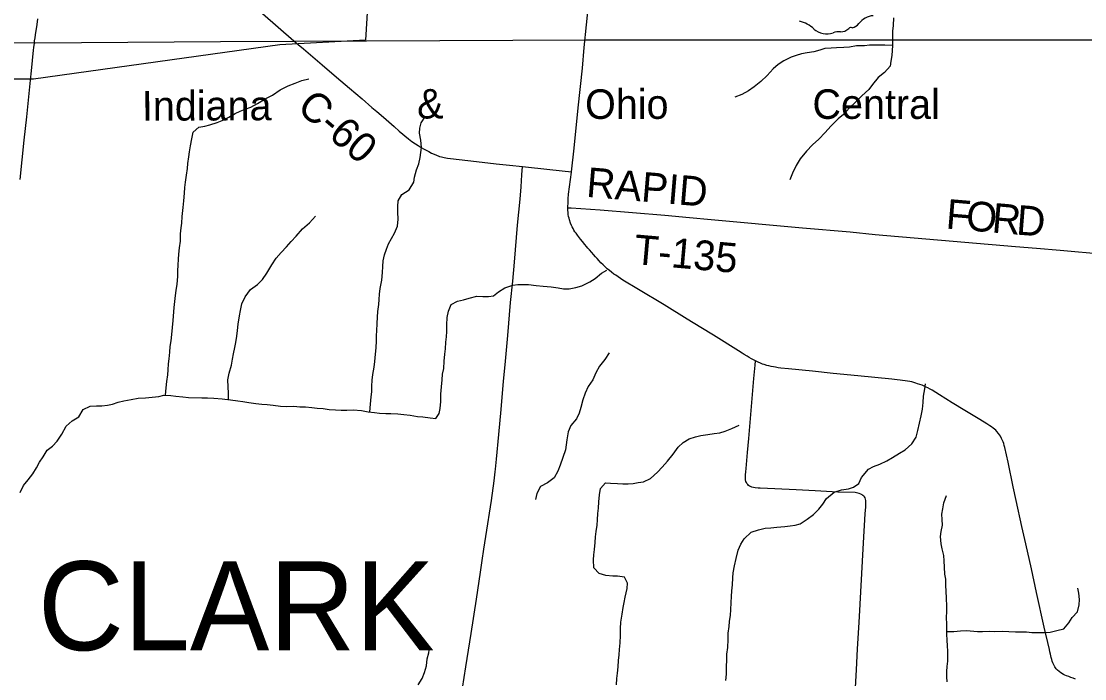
# Model space of a CAD drawing. Extents: x 1442749 to 1756758, y 235267 to 677782.
# Drawn here: x 1596416 to 1607177, y 476949 to 483604 of the extents above; entities that cross this region are included whole.
import ezdxf

# ---------------------------------------------------------------- set-up
doc = ezdxf.new("R2010")
doc.units = 0
for name, color, linetype in [('GM_X_City_Street', 7, 'Continuous'), ('GM_X_Corporation', 7, 'Continuous'), ('GM_X_County_Road', 7, 'Continuous'), ('GM_X_County_Road_Text', 7, 'Continuous'), ('GM_X_Minor_River', 7, 'Continuous'), ('GM_X_Rail_Line', 7, 'Continuous'), ('GM_X_Rail_Line_Text', 7, 'Continuous'), ('GM_X_State_Route', 7, 'Continuous'), ('GM_X_State_Shield', 7, 'Continuous'), ('GM_X_Township_Road', 7, 'Continuous'), ('GM_X_Township_Road_Text', 7, 'Continuous'), ('GM_X_Township_Text', 7, 'Continuous')]:
    doc.layers.add(name, color=color, linetype=linetype)

msp = doc.modelspace()

# ---------------------------------------------------------------- linework, layer by layer
at = {"layer": 'GM_X_City_Street'}
for points in [[(1598415, 484068), (1598535, 483962), (1598604, 483902), (1598646, 483865), (1598760, 483766), (1598857, 483682), (1599175, 483407), (1599219, 483370)], [(1596520, 483102), (1596541, 483311), (1596544, 483338), (1596550, 483383), (1596552, 483406), (1596556, 483437), (1596560, 483467), (1596563, 483490), (1596569, 483527), (1596576, 483571), (1596585, 483629)]]:
    msp.add_lwpolyline(points, dxfattribs=at)
at = {"layer": 'GM_X_Corporation'}
msp.add_lwpolyline([(1595505, 486015), (1596757, 485922), (1597610, 485853), (1597573, 485513), (1598676, 485417), (1598643, 485013), (1599988, 484861), (1599899, 483414), (1599034, 483364), (1596541, 483017), (1595600, 483017), (1595370, 485047)], close=True, dxfattribs=at)
at = {"layer": 'GM_X_County_Road'}
for points in [[(1599219, 483370), (1599271, 483325)], [(1599271, 483325), (1599462, 483163), (1599607, 483039), (1599739, 482927), (1599867, 482818), (1599965, 482732), (1600013, 482691), (1600080, 482633), (1600188, 482538), (1600240, 482493), (1600334, 482415), (1600370, 482387), (1600405, 482363), (1600432, 482346), (1600464, 482327), (1600487, 482314), (1600519, 482296), (1600540, 482285), (1600568, 482270), (1600611, 482251), (1600648, 482237), (1600667, 482231), (1600696, 482225), (1600730, 482220), (1600761, 482215), (1600846, 482204), (1601022, 482184), (1601220, 482161), (1601357, 482147), (1601488, 482133), (1601488, 482133)], [(1596405, 482001), (1596445, 482400), (1596472, 482638), (1596510, 483007), (1596520, 483102)], [(1600882, 476853), (1600915, 477070), (1600968, 477407), (1601021, 477754), (1601062, 478027), (1601081, 478147), (1601098, 478260), (1601118, 478390), (1601173, 478753), (1601201, 478951), (1601212, 479045), (1601215, 479072), (1601219, 479106), (1601225, 479173), (1601247, 479421), (1601271, 479676), (1601297, 479960), (1601312, 480127), (1601339, 480424), (1601368, 480757), (1601389, 480973), (1601408, 481165), (1601438, 481541), (1601463, 481802), (1601473, 481930), (1601482, 482051), (1601488, 482133)], [(1601488, 482133), (1601765, 482103), (1601984, 482079)], [(1604841, 476563), (1604867, 477038), (1604879, 477251), (1604894, 477520), (1604940, 478325), (1604957, 478620), (1604962, 478689), (1604963, 478716), (1604963, 478736), (1604962, 478753), (1604959, 478768), (1604955, 478780), (1604949, 478789), (1604941, 478798), (1604933, 478805), (1604924, 478812), (1604912, 478818), (1604896, 478825), (1604880, 478829), (1604868, 478831), (1604853, 478833), (1604679, 478839), (1604450, 478851), (1604256, 478860), (1604040, 478870), (1603892, 478878), (1603873, 478880), (1603843, 478883), (1603825, 478885), (1603809, 478889), (1603796, 478894), (1603786, 478900), (1603776, 478906), (1603767, 478915), (1603758, 478927), (1603753, 478937), (1603749, 478947), (1603746, 478962), (1603745, 478972), (1603744, 478984), (1603744, 479000), (1603745, 479013), (1603747, 479043), (1603751, 479079), (1603765, 479239), (1603777, 479382), (1603829, 479987), (1603843, 480124), (1603847, 480166)]]:
    msp.add_lwpolyline(points, dxfattribs=at)
at = {"layer": 'GM_X_Minor_River'}
for points in [[(1605241, 483638), (1605238, 483562), (1605233, 483503), (1605231, 483441), (1605232, 483359), (1605229, 483307), (1605224, 483257), (1605215, 483199), (1605209, 483149), (1605152, 483086), (1605087, 483034), (1605030, 482965), (1604993, 482913), (1604920, 482850), (1604857, 482785), (1604798, 482729), (1604737, 482662), (1604682, 482615), (1604607, 482541), (1604550, 482478), (1604485, 482411), (1604422, 482353), (1604361, 482288), (1604298, 482211), (1604257, 482143), (1604220, 482067)], [(1605232, 483359), (1605155, 483362), (1605069, 483361), (1604999, 483362), (1604949, 483357), (1604867, 483354), (1604796, 483343), (1604738, 483338), (1604666, 483336), (1604612, 483333), (1604547, 483328), (1604497, 483311), (1604435, 483295), (1604368, 483284), (1604312, 483273), (1604258, 483258), (1604205, 483240), (1604133, 483203), (1604076, 483166), (1604025, 483124), (1603964, 483055), (1603901, 482994), (1603832, 482940), (1603774, 482899), (1603707, 482864), (1603638, 482835)], [(1597875, 479818), (1597882, 479895), (1597891, 479957), (1597899, 480025), (1597904, 480075), (1597907, 480137), (1597914, 480187), (1597921, 480255), (1597923, 480311), (1597932, 480369), (1597941, 480435), (1597948, 480503), (1597953, 480577), (1597965, 480707), (1597971, 480767), (1597978, 480829), (1597985, 480879), (1597994, 480943), (1597999, 481020), (1598002, 481078), (1598004, 481134), (1598007, 481196), (1598012, 481246), (1598017, 481312), (1598026, 481380), (1598029, 481452), (1598036, 481512), (1598040, 481562), (1598045, 481628), (1598054, 481718), (1598061, 481788), (1598068, 481865), (1598073, 481923), (1598078, 481977), (1598087, 482045), (1598098, 482115), (1598102, 482165), (1598111, 482231), (1598118, 482283), (1598129, 482345), (1598142, 482413), (1598155, 482483), (1598214, 482532), (1598274, 482543), (1598324, 482555), (1598397, 482578), (1598465, 482607), (1598516, 482632), (1598580, 482672), (1598631, 482693), (1598681, 482716), (1598740, 482736), (1598808, 482771), (1598883, 482818), (1598958, 482855), (1599035, 482910), (1599116, 482951), (1599188, 482978), (1599257, 483006), (1599327, 483021)], [(1599945, 479650), (1599949, 479728), (1599958, 479802), (1599963, 479854), (1599964, 479912), (1599966, 479970), (1599975, 480030), (1599986, 480104), (1599995, 480160), (1600002, 480234), (1600007, 480300), (1600010, 480368), (1600011, 480422), (1600013, 480472), (1600018, 480546), (1600021, 480609), (1600026, 480665), (1600035, 480737), (1600037, 480787), (1600040, 480843), (1600047, 480899), (1600064, 480983), (1600073, 481061), (1600074, 481121), (1600079, 481181), (1600092, 481239), (1600112, 481297), (1600131, 481351), (1600162, 481404), (1600193, 481460), (1600222, 481530), (1600231, 481602), (1600228, 481672), (1600226, 481730), (1600231, 481788), (1600268, 481852), (1600341, 481899), (1600390, 481975), (1600395, 482025), (1600414, 482101), (1600439, 482161), (1600454, 482224), (1600467, 482325), (1600460, 482401), (1600445, 482473), (1600450, 482523), (1600464, 482575), (1600505, 482643)], [(1604220, 482067), (1604193, 482000)], [(1598512, 479776), (1598513, 479840), (1598510, 479905), (1598508, 479975), (1598521, 480043), (1598545, 480125), (1598555, 480183), (1598564, 480237), (1598579, 480301), (1598588, 480353), (1598597, 480417), (1598603, 480473), (1598612, 480539), (1598623, 480623), (1598634, 480677), (1598649, 480745), (1598682, 480816), (1598737, 480888), (1598808, 480939), (1598859, 480990), (1598900, 481056), (1598951, 481140), (1598994, 481207), (1599045, 481265), (1599100, 481320), (1599149, 481374), (1599198, 481429), (1599263, 481502), (1599334, 481564), (1599393, 481633)], [(1600646, 479634), (1600655, 479686), (1600661, 479756), (1600662, 479831), (1600667, 479905), (1600674, 479975), (1600679, 480033), (1600692, 480091), (1600695, 480163), (1600702, 480235), (1600709, 480287), (1600714, 480355), (1600718, 480411), (1600721, 480465), (1600724, 480533), (1600727, 480605), (1600738, 480671), (1600767, 480739), (1600829, 480770), (1600892, 480784), (1600950, 480803), (1601027, 480822), (1601087, 480819), (1601143, 480819), (1601195, 480826), (1601246, 480865), (1601308, 480905), (1601389, 480934), (1601441, 480939), (1601497, 480940), (1601550, 480940), (1601626, 480931), (1601696, 480922), (1601778, 480915), (1601848, 480906), (1601904, 480897), (1601960, 480896), (1602029, 480911), (1602087, 480927), (1602168, 480968), (1602222, 481001), (1602287, 481056), (1602340, 481086)], [(1602365, 480249), (1602320, 480182), (1602267, 480114), (1602230, 480047), (1602201, 479975), (1602154, 479907), (1602121, 479840), (1602100, 479772), (1602077, 479694), (1602062, 479638), (1602033, 479580), (1601976, 479513), (1601949, 479447), (1601938, 479369), (1601931, 479317), (1601924, 479265), (1601897, 479189), (1601868, 479111), (1601845, 479050), (1601810, 478982), (1601742, 478933), (1601669, 478896), (1601632, 478826), (1601619, 478762)], [(1603593, 477592), (1603596, 477648), (1603601, 477720), (1603603, 477782), (1603606, 477838), (1603613, 477900), (1603618, 477970), (1603621, 478020), (1603634, 478092), (1603651, 478166), (1603670, 478250), (1603697, 478312), (1603732, 478366), (1603803, 478433), (1603877, 478458), (1603944, 478475), (1604000, 478478), (1604062, 478482), (1604144, 478491), (1604197, 478496), (1604247, 478503), (1604299, 478519), (1604368, 478564), (1604431, 478611), (1604488, 478667), (1604526, 478718), (1604563, 478774), (1604640, 478839), (1604715, 478860), (1604787, 478871), (1604837, 478887), (1604892, 478926), (1604919, 478988), (1604990, 479071), (1605041, 479096), (1605103, 479122), (1605176, 479155), (1605233, 479190), (1605303, 479231), (1605360, 479267), (1605429, 479328), (1605472, 479393), (1605489, 479463), (1605504, 479537), (1605523, 479609), (1605534, 479679), (1605543, 479745), (1605546, 479811), (1605559, 479883), (1605565, 479933)], [(1596406, 478835), (1596439, 478907), (1596485, 478963), (1596532, 479022), (1596571, 479084), (1596602, 479140), (1596637, 479197), (1596678, 479263), (1596731, 479302), (1596781, 479354), (1596827, 479425), (1596872, 479505), (1596931, 479560), (1596999, 479601), (1597044, 479675), (1597115, 479708), (1597179, 479711), (1597231, 479711), (1597288, 479718), (1597338, 479729), (1597398, 479749), (1597453, 479762), (1597527, 479777), (1597599, 479788), (1597672, 479791), (1597740, 479800), (1597808, 479807), (1597859, 479819), (1597929, 479816), (1597981, 479811), (1598051, 479802), (1598107, 479796), (1598243, 479794), (1598301, 479791), (1598366, 479790), (1598450, 479783), (1598534, 479774), (1598608, 479761), (1598660, 479754), (1598720, 479747), (1598790, 479737), (1598850, 479730), (1598906, 479725), (1598964, 479720), (1599040, 479709), (1599105, 479706), (1599175, 479708), (1599235, 479703), (1599291, 479700), (1599355, 479695), (1599409, 479688), (1599471, 479684), (1599533, 479675), (1599595, 479670), (1599654, 479667), (1599710, 479669), (1599776, 479670), (1599858, 479663), (1599926, 479652), (1599992, 479645), (1600042, 479638), (1600104, 479633), (1600156, 479633), (1600227, 479630), (1600287, 479625), (1600351, 479618), (1600427, 479605), (1600479, 479600), (1600553, 479589), (1600611, 479583), (1600646, 479634)], [(1602558, 478922), (1602608, 478927), (1602660, 478937), (1602714, 478944), (1602783, 478977), (1602854, 479039), (1602901, 479090), (1602956, 479153), (1603013, 479223), (1603062, 479292), (1603115, 479342), (1603175, 479377), (1603238, 479398), (1603294, 479412), (1603362, 479421), (1603427, 479430), (1603485, 479437), (1603539, 479455), (1603606, 479482), (1603679, 479517)], [(1602438, 476887), (1602443, 476951), (1602450, 477005), (1602457, 477071), (1602460, 477133), (1602467, 477191), (1602469, 477246), (1602476, 477314), (1602481, 477388), (1602480, 477458), (1602483, 477522), (1602496, 477604), (1602507, 477670), (1602516, 477722), (1602528, 477774), (1602546, 477864), (1602552, 477918), (1602521, 477978), (1602451, 477987), (1602401, 477988), (1602333, 477993), (1602265, 478014), (1602211, 478073), (1602205, 478153), (1602209, 478203), (1602218, 478259), (1602225, 478329), (1602228, 478385), (1602234, 478439), (1602243, 478505), (1602248, 478559), (1602251, 478623), (1602256, 478677), (1602260, 478740), (1602267, 478812), (1602276, 478876), (1602329, 478931), (1602379, 478928), (1602451, 478925), (1602502, 478923), (1602558, 478922)], [(1605786, 476918), (1605783, 476968), (1605781, 477022), (1605786, 477074), (1605791, 477128), (1605792, 477229), (1605789, 477281), (1605786, 477339), (1605782, 477399), (1605783, 477451), (1605782, 477501), (1605779, 477569), (1605783, 477630), (1605780, 477688), (1605777, 477760), (1605776, 477838), (1605773, 477890), (1605770, 477956), (1605762, 478007), (1605759, 478079), (1605756, 478143), (1605751, 478197), (1605734, 478264), (1605726, 478314), (1605719, 478390), (1605726, 478440), (1605739, 478504), (1605736, 478560), (1605732, 478614), (1605741, 478670), (1605750, 478730), (1605779, 478804)], [(1605783, 477427), (1605851, 477428), (1605919, 477433), (1605979, 477437), (1606092, 477427), (1606144, 477428), (1606210, 477430), (1606268, 477429), (1606344, 477432), (1606409, 477429), (1606477, 477424), (1606589, 477423), (1606641, 477418), (1606711, 477417), (1606771, 477418), (1606828, 477422), (1606896, 477437), (1606964, 477454), (1607017, 477515), (1607050, 477569), (1607103, 477628), (1607122, 477698), (1607125, 477750), (1607118, 477815), (1607106, 477867)], [(1603546, 476931), (1603553, 476995), (1603552, 477077), (1603555, 477133), (1603556, 477197), (1603565, 477267), (1603568, 477346), (1603570, 477410), (1603579, 477478), (1603584, 477530), (1603593, 477592)], [(1600433, 476887), (1600472, 476953), (1600495, 477011), (1600516, 477080), (1600525, 477150), (1600539, 477212), (1600546, 477264)]]:
    msp.add_lwpolyline(points, dxfattribs=at)
at = {"layer": 'GM_X_Rail_Line'}
msp.add_lwpolyline([(1571148, 478363), (1571889, 478539), (1575743, 479319), (1579466, 480096), (1583642, 480978), (1587511, 481783), (1590382, 482359), (1593451, 482999), (1594964, 483308), (1595339, 483357), (1595650, 483379), (1596034, 483391), (1596557, 483385), (1598434, 483400), (1602128, 483416), (1606202, 483416), (1608267, 483417), (1610514, 483462), (1613925, 483518), (1615664, 483549), (1619432, 483601)], dxfattribs=at)
at = {"layer": 'GM_X_State_Route'}
msp.add_lwpolyline([(1607084, 476945), (1607060, 476954), (1607035, 476963), (1607015, 476971), (1606992, 476980), (1606976, 476987), (1606962, 476994), (1606936, 477009), (1606917, 477023), (1606902, 477036), (1606888, 477051), (1606875, 477071), (1606863, 477091), (1606854, 477112), (1606848, 477129), (1606843, 477144), (1606838, 477164), (1606834, 477182), (1606830, 477198), (1606825, 477221), (1606819, 477246), (1606768, 477473), (1606690, 477822), (1606638, 478063), (1606581, 478316), (1606541, 478491), (1606484, 478754), (1606454, 478892), (1606401, 479142), (1606368, 479290), (1606362, 479310), (1606357, 479330), (1606350, 479347), (1606346, 479361), (1606336, 479382), (1606324, 479404), (1606315, 479418), (1606306, 479431), (1606287, 479453), (1606276, 479464), (1606263, 479475), (1606249, 479487), (1606233, 479498), (1606217, 479510), (1606187, 479529), (1606117, 479572), (1605965, 479664), (1605837, 479743), (1605709, 479824), (1605634, 479870), (1605613, 479881), (1605591, 479893), (1605573, 479902), (1605552, 479911), (1605531, 479920), (1605510, 479928), (1605486, 479936), (1605467, 479942), (1605447, 479947), (1605426, 479953), (1605407, 479957), (1605384, 479961), (1605359, 479965), (1605333, 479969), (1605310, 479972), (1605278, 479976), (1605251, 479979), (1605224, 479981), (1604882, 480015), (1604631, 480040), (1604422, 480061), (1604181, 480085), (1604102, 480094), (1604074, 480098), (1604047, 480102), (1604027, 480106), (1604005, 480110), (1603982, 480115), (1603960, 480121), (1603935, 480129), (1603916, 480135), (1603895, 480144), (1603873, 480153), (1603854, 480163), (1603847, 480166), (1603832, 480174), (1603805, 480188), (1603783, 480201), (1603762, 480213), (1603732, 480231), (1603710, 480245), (1603675, 480267), (1603420, 480426), (1603292, 480505), (1603155, 480589), (1602920, 480733), (1602662, 480890), (1602505, 480985), (1602455, 481017), (1602431, 481033), (1602411, 481046), (1602389, 481063), (1602367, 481080), (1602344, 481100), (1602320, 481122), (1602303, 481138), (1602282, 481159), (1602264, 481179), (1602242, 481202), (1602226, 481220), (1602205, 481244), (1602188, 481264), (1602165, 481291), (1602149, 481309), (1602137, 481324), (1602120, 481344), (1602095, 481375), (1602074, 481400), (1602043, 481439), (1602030, 481459), (1602019, 481474), (1602009, 481491), (1602000, 481506), (1601992, 481523), (1601984, 481538), (1601974, 481562), (1601963, 481594), (1601959, 481611), (1601954, 481629), (1601951, 481649), (1601949, 481671), (1601948, 481689), (1601947, 481712), (1601947, 481717), (1601947, 481732), (1601949, 481759), (1601950, 481784), (1601951, 481806), (1601955, 481853), (1601963, 481928), (1601983, 482078), (1601984, 482079), (1602012, 482319), (1602053, 482727), (1602094, 483131), (1602113, 483337), (1602136, 483569), (1602161, 483833)], dxfattribs=at)
at = {"layer": 'GM_X_State_Shield'}
for centre, radius, start, end in [((1604210, 483281), 334, 47.1842, 75.836), ((1604797, 483653), 119, 282.8732, 323.2771), ((1605053, 483459), 202, 94.4031, 142.5768), ((1604571, 483689), 212, 230.7004, 286.2918), ((1604693, 483324), 174, 85.6951, 111.2099), ((1604708, 483610), 113, 268.777, 315.5493), ((1604811, 483508), 31.8, 65.7517, 132.6484)]:
    msp.add_arc(centre, radius, start, end, dxfattribs=at)
at = {"layer": 'GM_X_Township_Road'}
msp.add_lwpolyline([(1601947, 481717), (1601980, 481715), (1602275, 481696), (1602929, 481640), (1603178, 481618), (1603397, 481599), (1604322, 481514), (1604802, 481473), (1605056, 481447), (1605963, 481368), (1606475, 481326), (1606688, 481308), (1606927, 481287), (1607377, 481246), (1608024, 481190), (1608613, 481134), (1608622, 481133)], dxfattribs=at)

# ---------------------------------------------------------------- texts
at = {"layer": 'GM_X_County_Road_Text'}
msp.add_text('C-60', height=300, rotation=319.3653, dxfattribs=at).set_placement((1599192, 482711))
at = {"layer": 'GM_X_Rail_Line_Text'}
for s, rotation, p in [('Ohio', 0, (1602121, 482616)), ('Central', 0, (1604422, 482616)), ('Indiana', 0.1716, (1597637, 482598)), ('&', 0, (1600422, 482620))]:
    msp.add_text(s, height=299, rotation=rotation, dxfattribs=at).set_placement(p)
at = {"layer": 'GM_X_Township_Road_Text'}
for s, rotation, p in [('RAPID', 355.2171, (1602127, 481828)), ('F', 355.1476, (1605765, 481507)), ('O', 355.1456, (1605967, 481490)), ('R', 355.1465, (1606230, 481467)), ('D', 355.5745, (1606478, 481446)), ('T-135', 354.957, (1602607, 481148))]:
    msp.add_text(s, height=300, rotation=rotation, dxfattribs=at).set_placement(p)
at = {"layer": 'GM_X_Township_Text'}
msp.add_text('CLARK', height=900, rotation=0, dxfattribs=at).set_placement((1596585, 477238))

doc.saveas('drawing.dxf')
